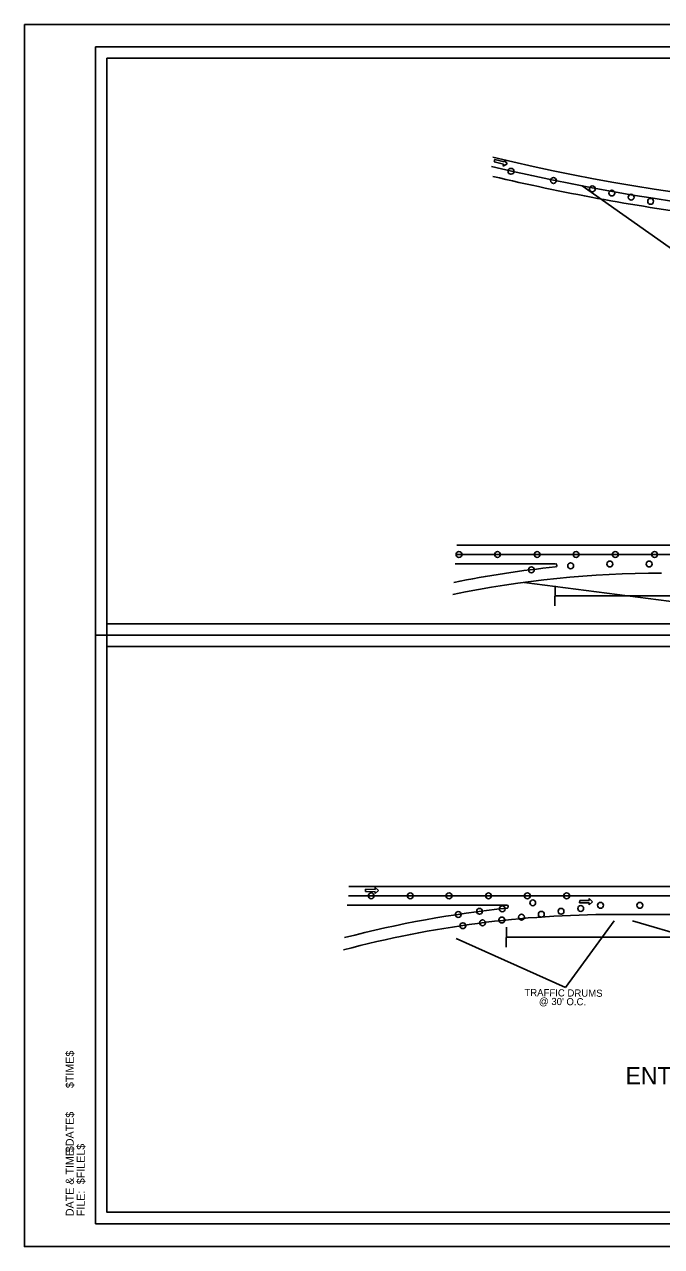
# Model space of a CAD drawing. Extents: x -500 to 213, y 382723 to 382830.
# Drawn here: x -135.6 to -79.9, y 382723.1 to 382829.8 of the extents above; entities that cross this region are included whole.
import ezdxf

# ---------------------------------------------------------------- set-up
doc = ezdxf.new("R2010")
doc.units = 0
for name, color, linetype in [('Default', 7, 'Continuous'), ('R_Border', 7, 'Continuous'), ('R_Border Notes', 7, 'Continuous'), ('R_Border Plan-Plan', 7, 'Continuous'), ('R_MOT', 7, 'Continuous'), ('R_No Plot', 7, 'Continuous')]:
    doc.layers.add(name, color=color, linetype=linetype)

# ---------------------------------------------------------------- blocks, each defined once
blk = doc.blocks.new('DOT')
at = {"layer": 'Default'}
blk.add_circle((-0.4, -0.3), 3.75, dxfattribs=at)
blk = doc.blocks.new('SARROW')
at = {"layer": 'Default'}
for p, q in [((15.6, 3.2), (-13.8, 3.2)), ((-13.8, 3.2), (-13.8, -2.8)), ((15.6, 8.2), (15.6, 3.2)), ((15.6, 8.2), (26, 0.2)), ((26, 0.2), (15.6, -7.8)), ((15.6, -2.8), (-13.8, -2.8)), ((15.6, -2.8), (15.6, -7.8))]:
    blk.add_line(p, q, dxfattribs=at)

msp = doc.modelspace()

# ---------------------------------------------------------------- linework, layer by layer
at = {"layer": 'Default'}
for p, q in [((-97.81, 382784.35), (6.37, 382784.35)), ((-97.83, 382783.53), (6.35, 382783.53)), ((-97.94, 382782.72), (-89.18, 382782.72)), ((-89.26, 382779.05), (-89.22, 382780.79)), ((-89.24, 382779.92), (-24.32, 382779.92)), ((-107.24, 382754.56), (2.89, 382754.56)), ((-107.26, 382753.75), (2.87, 382753.75)), ((-107.38, 382752.93), (-102.61, 382752.93)), ((-102.61, 382752.93), (-93.43, 382752.93)), ((-84.18, 382752.11), (-28.53, 382752.11)), ((-93.51, 382749.26), (-93.47, 382751)), ((-93.49, 382750.13), (-28.56, 382750.13))]:
    msp.add_line(p, q, dxfattribs=at)
for centre, major_axis, start_param, end_param in [((-52.59, 383072.52), (0, 260.09), 2.945637, 3.209664), ((-52.59, 383072.52), (0, 259.28), 2.945637, 3.209664), ((-52.59, 383072.52), (0, 260.91), 2.94688, 3.032274), ((-83.15, 382652.5), (10.65, 130.12), 0.153253, 0.235336), ((-89.18, 382782.58), (0.011, 0.136), 3.294846, 6.351257), ((-83.15, 382652.5), (10.56, 129.1), 0.068125, 0.237227), ((-87.39, 382622.71), (10.65, 130.12), 0.153253, 0.284497), ((-93.43, 382752.79), (0.011, 0.136), 3.294846, 6.351257), ((-87.39, 382622.71), (10.56, 129.1), 0.068125, 0.286803)]:
    msp.add_ellipse(centre, major_axis=major_axis, ratio=0.833333, start_param=start_param, end_param=end_param, dxfattribs=at)
at = {"layer": 'R_Border'}
for p, q in [((-129.35, 382827.85), (28.74, 382827.85)), ((-129.35, 382725.12), (-129.35, 382827.85)), ((-129.35, 382725.12), (-129.35, 382725.12)), ((28.74, 382725.12), (-129.35, 382725.12))]:
    msp.add_line(p, q, dxfattribs=at)
at = {"layer": 'R_Border Plan-Plan'}
msp.add_line((-129.35, 382776.49), (28.74, 382776.49), dxfattribs=at)
at = {"layer": 'R_MOT'}
for p, q in [((-86.86, 382815.7), (-74.26, 382806.8)), ((-91.94, 382781.1), (-52.26, 382775.94)), ((-84.06, 382751.57), (-88.32, 382745.75)), ((-82.48, 382751.57), (-59.64, 382744.86)), ((-97.87, 382750.02), (-88.32, 382745.75))]:
    msp.add_line(p, q, dxfattribs=at)
at = {"layer": 'R_No Plot'}
for points in [[(-135.56, 382829.8), (31.11, 382829.8), (31.11, 382723.13), (-135.56, 382723.13)], [(27.74, 382777.49), (-128.35, 382777.49), (-128.35, 382826.85), (-3.58, 382826.85), (-3.58, 382821.91), (5.19, 382821.91), (17.24, 382821.91), (17.24, 382810.74), (27.74, 382810.74)], [(-128.35, 382826.85), (-3.58, 382826.85), (-3.58, 382821.91), (5.19, 382821.91), (17.24, 382821.91), (17.24, 382810.74), (27.74, 382810.74), (27.74, 382726.12), (-128.35, 382726.12)], [(-128.35, 382775.49), (27.74, 382775.49), (27.74, 382726.12), (-128.35, 382726.12)]]:
    msp.add_lwpolyline(points, close=True, dxfattribs=at)

# ---------------------------------------------------------------- block references
at = {"layer": 'R_MOT'}
for name, p, xscale, yscale, rotation in [('SARROW', (-94.14, 382817.8), 0.028614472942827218, 0.0337572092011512, -13.600455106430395), ('DOT', (-97.59, 382783.55), 0.06809210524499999, 0.06809210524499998, -4.676990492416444), ('DOT', (-94.22, 382783.55), 0.06809210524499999, 0.06809210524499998, -4.676990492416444), ('DOT', (-90.76, 382783.55), 0.06809210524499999, 0.06809210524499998, -4.676990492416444), ('DOT', (-87.37, 382783.55), 0.06809210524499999, 0.06809210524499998, -4.676990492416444), ('DOT', (-83.94, 382783.55), 0.06809210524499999, 0.06809210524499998, -4.676990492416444), ('DOT', (-80.51, 382783.55), 0.06809210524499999, 0.06809210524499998, -4.676990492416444), ('DOT', (-91.27, 382782.21), 0.06809210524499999, 0.06809210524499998, -4.676990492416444), ('DOT', (-87.84, 382782.57), 0.06809210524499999, 0.06809210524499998, -4.676990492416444), ('DOT', (-84.42, 382782.72), 0.06809210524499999, 0.06809210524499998, -4.676990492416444), ('DOT', (-80.99, 382782.72), 0.06809210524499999, 0.06809210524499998, -4.676990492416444), ('SARROW', (-105.38, 382754.2), 0.0283940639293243, 0.034019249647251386, -0.5613379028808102), ('DOT', (-105.25, 382753.76), 0.06809210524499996, 0.06809210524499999, -4.676990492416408), ('DOT', (-101.84, 382753.76), 0.06809210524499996, 0.06809210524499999, -4.676990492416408), ('DOT', (-98.46, 382753.76), 0.06809210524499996, 0.06809210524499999, -4.676990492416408), ('DOT', (-95.01, 382753.76), 0.06809210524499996, 0.06809210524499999, -4.676990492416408), ('DOT', (-91.62, 382753.76), 0.06809210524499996, 0.06809210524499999, -4.676990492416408), ('DOT', (-91.15, 382753.15), 0.06809210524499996, 0.06809210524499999, -4.676990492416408), ('DOT', (-88.19, 382753.76), 0.06809210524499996, 0.06809210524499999, -4.676990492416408), ('SARROW', (-86.69, 382753.22), 0.028398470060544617, 0.03401397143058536, -0.17370681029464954), ('DOT', (-97.65, 382752.13), 0.06809210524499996, 0.06809210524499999, -4.676990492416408), ('DOT', (-95.79, 382752.41), 0.06809210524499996, 0.06809210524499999, -4.676990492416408), ('DOT', (-93.81, 382752.62), 0.06809210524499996, 0.06809210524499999, -4.676990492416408), ('DOT', (-90.4, 382752.15), 0.06809210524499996, 0.06809210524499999, -4.676990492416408), ('DOT', (-88.68, 382752.41), 0.06809210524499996, 0.06809210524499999, -4.676990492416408), ('DOT', (-86.96, 382752.66), 0.06809210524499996, 0.06809210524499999, -4.676990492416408), ('DOT', (-85.24, 382752.93), 0.06809210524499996, 0.06809210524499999, -4.676990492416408), ('DOT', (-81.8, 382752.93), 0.06809210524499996, 0.06809210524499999, -4.676990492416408), ('DOT', (-97.25, 382751.15), 0.06809210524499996, 0.06809210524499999, -4.676990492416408), ('DOT', (-95.53, 382751.41), 0.06809210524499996, 0.06809210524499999, -4.676990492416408), ('DOT', (-93.85, 382751.65), 0.06809210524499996, 0.06809210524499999, -4.676990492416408), ('DOT', (-92.13, 382751.9), 0.06809210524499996, 0.06809210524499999, -4.676990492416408)]:
    msp.add_blockref(name, p, dxfattribs=dict(at, xscale=xscale, yscale=yscale, rotation=rotation))
at = {"layer": 'R_MOT', "xscale": 0.06809210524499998, "yscale": 0.06809210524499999}
for p in [(-93.05, 382817), (-89.34, 382816.19), (-85.95, 382815.47), (-84.25, 382815.1), (-82.56, 382814.74), (-80.86, 382814.38)]:
    msp.add_blockref('DOT', p, dxfattribs=at)

# ---------------------------------------------------------------- texts
at = {"layer": 'R_Border Notes'}
for s, height, p in [('$TIME$', 0.698, (-131.25, 382736.96)), ('$DATE$', 0.698, (-131.25, 382731.37)), ('$FILEL$', 0.698, (-130.29, 382728.57)), ('DATE & TIME:', 0.6984, (-131.25, 382725.78)), ('FILE: ', 0.698, (-130.29, 382725.78))]:
    msp.add_text(s, height=height, rotation=90, dxfattribs=at).set_placement(p)
at = {"layer": 'R_MOT'}
for s, p in [('TRAFFIC DRUMS ', (-91.91, 382744.99)), ("@ 30' O.C.", (-90.64, 382744.22))]:
    msp.add_text(s, height=0.625, rotation=359.4579, dxfattribs=at).set_placement(p)
msp.add_text('ENTRANCE RAMP - TYPICAL TRAFFIC DRUM LAYOUT', height=1.5, dxfattribs=at).set_placement((-83.08, 382737.29))

doc.saveas('drawing.dxf')
